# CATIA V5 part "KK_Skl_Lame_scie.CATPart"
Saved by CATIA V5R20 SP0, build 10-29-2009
Part number: Skl_Lame_scie
Publications: "Droite.4", "Axe_pivot_Scie_biellette", "Point.2", "Point.3", "Plan.Ref5", "Plan_Ref1"
Bounding box of the stored display mesh (mm): x 2.5 to 22.5, y 135 to 335, z 0 to 0
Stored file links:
  G:\Khaled_CFAO_2011\ST2M\ST2M_GR2\aandujar\Khaled\CAD_thinkMOTION\KK_Skl_Lame_scie.CATPart
  G:\Khaled_CFAO_2011\ST2M\ST2M_GR2\aandujar\Khaled\CAD_thinkMOTION\KK_Skl_scie_mecanique.CATProduct
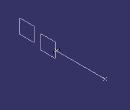
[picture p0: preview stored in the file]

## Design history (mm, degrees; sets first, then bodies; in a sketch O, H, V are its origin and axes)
WSupportSet1: ActiveGrid {3dwsupport RefPoint {point stored without definition}, 3DWOS ({wsupport Support xy-plane, RefPoint {3dwsupport}, GridIn {cartgrid Value 100, Stepbid1 0, Value 100, Stepbid2 0, Direction (1, 0, 0)}, GeometricData ({line type PtDir, Direction (1, 0, 0), Support xy-plane}; {line type PtDir, Direction (0, 1, 0), Support yz-plane})}; {wsupport Support yz-plane, RefPoint {3dwsupport}, GridIn {cartgrid Value 100, Stepbid1 0, Value 100, Stepbid2 0, Direction (0, 1, 0)}, GeometricData ({line type PtDir, Direction (0, 1, 0), Support yz-plane}; {line type PtDir, Direction (0, 0, 1), Support zx-plane})}; {wsupport Support zx-plane, RefPoint {3dwsupport}, GridIn {cartgrid Value 100, Stepbid1 0, Value 100, Stepbid2 0, Direction (0, 0, 1)}, GeometricData ({line type PtDir, Direction (0, 0, 1), Support zx-plane}; {line type PtDir, Direction (1, 0, 0), Support xy-plane})}), GeometricData ({line type PtDir, RefPoint {point stored without definition}, Direction (1, 0, 0), Support xy-plane}; {line type PtDir, RefPoint {point stored without definition}, Direction (0, 1, 0), Support yz-plane}; {line type PtDir, RefPoint {point stored without definition}, Direction (0, 0, 1), Support zx-plane})}
Set1
  Line1: type PtPt, FirstPoint Point2, SecondPoint Point1
  Line2 "Axe_pivot_Scie_biellette": type Normal, RefPoint Point2, RefSkin Plane2, Start -10, End 10
Set2
  Point1: linked copy from another document
  Point2: linked copy from another document
  Plane1 "Plan.Ref5": linked copy from another document
  Plane2 "Plan_Ref1": linked copy from another document
Body1 (main body)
